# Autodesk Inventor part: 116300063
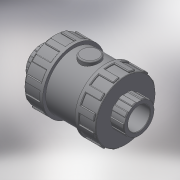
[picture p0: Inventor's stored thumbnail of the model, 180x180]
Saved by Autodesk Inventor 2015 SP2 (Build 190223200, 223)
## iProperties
Created: 2017-11
Part Number: 116300063
Material: Generic
Description: PLASSON AIR RELEASE VALVE CEM PVC 63
Document SubType Name: Modeling
Designer: KIM
Density: 1 g/cm^3
Appearance: Default
Author: KIM
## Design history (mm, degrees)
derived "116300 - 116900.ipt"
feature "Solid1::116300 - 116900.ipt"
tag "TaggingFeature1"
body "Solid1"
other parameters: "d0" = 169, "d1" = 63, "d2" = 118, "d3" = 38, "d4" = 50.4, "d5" = 26.6, "d7" = 88.2, "d8" = 106.2, "d13" = 1.89, "d23" = 38, "d24" = 113.28, "d25" = 1.26, "d26" = 1.89, "d27" = 17.7, "d28" = 8.85, "d29" = 28.5, "d30" = 0, "d35" = 1.89, "d39" = 59, "d45" = 360 deg, "d47" = 1.26, "d50" = 59, "d51" = 35.4, "d53" = 0, "d54" = 2.36, "d55" = 12.6, "d56" = 6.3, "d58" = 0, "d59" = 1.89, "d61" = 360 deg, "d_" = 63, "l_" = 38, "H_" = 169, "K_" = 118
